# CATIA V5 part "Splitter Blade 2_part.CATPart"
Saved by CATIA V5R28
Part number: Splitter Blade 2_part
Definition: design
Nomenclature: Splitter Blade 2_part
Source: Unknown
Bounding box of the stored display mesh (mm): x 3.629 to 6.778, y -7.597 to 1.198, z 4.237 to 7.742
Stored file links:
  D:\paraturbo-cad\STEP\Turbocompressor_for_Christophe\Splitter Blade 2_part.CATPart
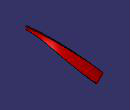
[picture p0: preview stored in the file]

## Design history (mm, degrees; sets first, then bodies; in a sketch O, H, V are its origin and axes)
Body1 "MANIFOLD_SOLID_BREP #62266" (main body)
  Solid1: solid without history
